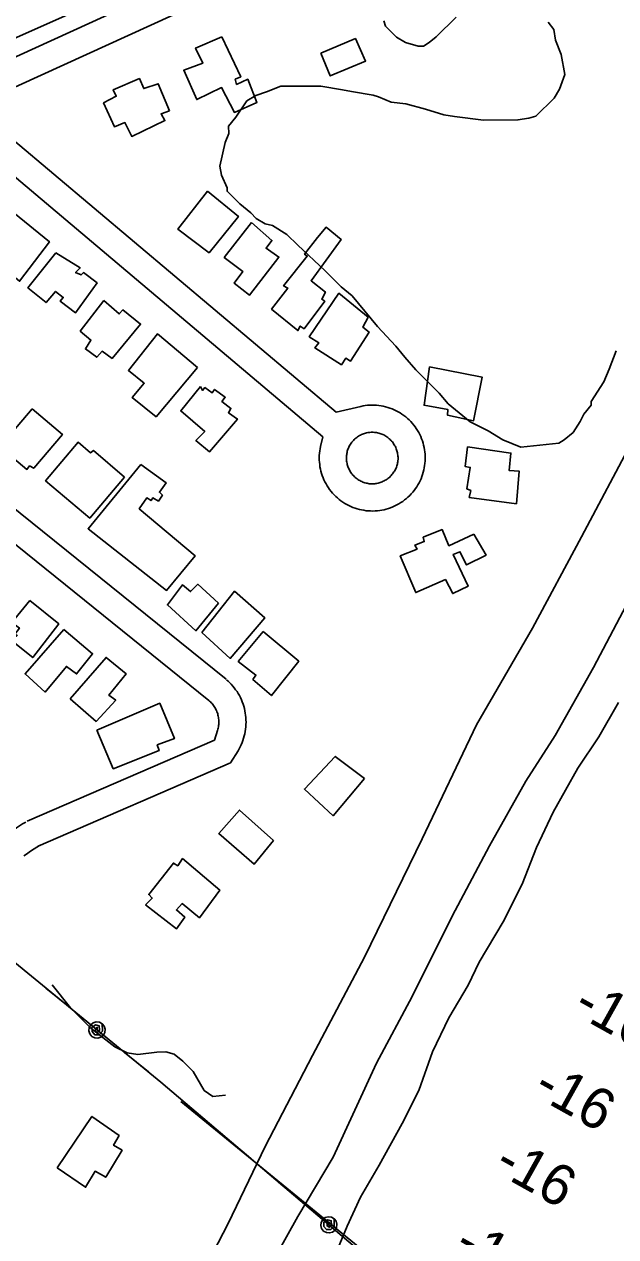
# Model space of a CAD drawing. Extents: x 3683402 to 3721514, y 487807 to 513565.
# Drawn here: x 3700485 to 3701138, y 502284 to 503622 of the extents above; entities that cross this region are included whole.
import ezdxf

# ---------------------------------------------------------------- set-up
doc = ezdxf.new("R2010")
doc.units = 0
for name, color, linetype in [('V-BLDG-OTLN', 7, 'Continuous'), ('V-LEVE-TOET', 7, 'Continuous'), ('V-ROAD-CNTR', 7, 'Continuous'), ('V-SITE-VEGE', 7, 'Continuous'), ('V-TOPO-SHOR', 7, 'Continuous'), ('V-TOPO-SPOT', 7, 'Continuous'), ('V-UTIL-LINE', 7, 'Continuous')]:
    doc.layers.add(name, color=color, linetype=linetype)

msp = doc.modelspace()

# ---------------------------------------------------------------- linework, layer by layer
at = {"layer": 'V-BLDG-OTLN'}
for points in [[(3700703.3, 503607.7), (3700724, 503563.7), (3700718, 503561), (3700719.5, 503555.3), (3700731.7, 503561), (3700741.9, 503535.5), (3700717, 503524.4), (3700702.9, 503551.7), (3700675.5, 503538.5), (3700661.1, 503570.9), (3700682.2, 503578.7), (3700674.2, 503595.4)], [(3700812.3, 503589.6), (3700850.6, 503605.8), (3700861.7, 503581.1), (3700822.8, 503564.6)], [(3700645.4, 503526.1), (3700636.2, 503522.8), (3700640.4, 503515.4), (3700603.8, 503498), (3700596.3, 503513.1), (3700584.7, 503508.6), (3700572.7, 503534.8), (3700586.7, 503542.3), (3700583.4, 503549.4), (3700612.2, 503561.7), (3700617, 503550.7), (3700633.1, 503556.1)], [(3700687.4, 503437.5), (3700721.4, 503409.7), (3700689.1, 503369.7), (3700654.5, 503395.8)], [(3700473.8, 503413.7), (3700512.9, 503381.7), (3700480, 503338.1), (3700439.7, 503371.3)], [(3700736, 503402.9), (3700758.4, 503383.3), (3700751.9, 503374.6), (3700766.2, 503364.9), (3700733.6, 503322.8), (3700716.6, 503336.1), (3700726.3, 503349), (3700705.8, 503364.4)], [(3700808.7, 503386.4), (3700818.2, 503397.8), (3700834.9, 503384.1), (3700801.7, 503338.8), (3700817.5, 503326.3), (3700813.4, 503318.3), (3700816.6, 503316.2), (3700793.8, 503285.8), (3700789.6, 503288.7), (3700787, 503283.7), (3700758, 503307.4), (3700775.8, 503330.7), (3700771.3, 503333.3), (3700797.4, 503365.9), (3700794.4, 503367.9)], [(3700520.1, 503369.5), (3700547, 503352.9), (3700541.9, 503347.8), (3700547.9, 503345.2), (3700550.5, 503347.8), (3700565.5, 503336.3), (3700541.8, 503303.5), (3700525, 503316.2), (3700528.3, 503320.4), (3700519.7, 503326.9), (3700509.3, 503314.7), (3700489.3, 503331)], [(3700864.6, 503298.5), (3700858.7, 503287.5), (3700865.6, 503282.1), (3700845.1, 503250.2), (3700840.1, 503253.5), (3700835, 503246), (3700805.8, 503264.7), (3700810.2, 503270.1), (3700799.5, 503276.9), (3700832.4, 503324.9)], [(3700573, 503317), (3700590, 503302.1), (3700594.1, 503306.6), (3700613.5, 503290.9), (3700582.1, 503253), (3700571.1, 503261), (3700565.1, 503254.4), (3700552.6, 503263.6), (3700558.8, 503273.2), (3700546.9, 503283.2)], [(3700676.4, 503243.1), (3700630.7, 503188.8), (3700604.2, 503210.1), (3700617.5, 503225.7), (3700600.2, 503239.9), (3700632.2, 503280.2)], [(3700932.4, 503243.7), (3700990.5, 503232.2), (3700980.8, 503184.3), (3700952.2, 503190.4), (3700952.5, 503196.7), (3700926.3, 503201.4)], [(3700679.7, 503222), (3700681.8, 503217.8), (3700684.5, 503220.8), (3700692.5, 503215.2), (3700695.2, 503218.8), (3700706.9, 503210.2), (3700703.3, 503205.7), (3700713.1, 503198), (3700710.5, 503193.2), (3700720.3, 503186.1), (3700689.5, 503150), (3700674.6, 503162.4), (3700684.4, 503172.6), (3700657.8, 503195.1)], [(3700493.9, 503197.6), (3700527.3, 503169.2), (3700495.6, 503131.9), (3700491.1, 503134.5), (3700488.1, 503130.6), (3700464.3, 503150.8), (3700466.6, 503153.5), (3700460.7, 503158.5)], [(3700595.9, 503122.1), (3700557.4, 503077), (3700508.7, 503118.2), (3700544.6, 503160.6), (3700558.3, 503149), (3700561.6, 503151.4)], [(3701028.1, 503092.8), (3700976, 503099.7), (3700977.8, 503107.2), (3700973.3, 503109.3), (3700977.1, 503132.8), (3700971.7, 503133.7), (3700974.3, 503155.4), (3701022, 503148.7), (3701020, 503129.6), (3701031, 503128.8)], [(3700613.8, 503136.1), (3700641.8, 503115.7), (3700634.4, 503105.5), (3700637.7, 503102.3), (3700633.2, 503095.7), (3700627, 503099.2), (3700625.2, 503096.3), (3700620.4, 503099.2), (3700612.1, 503087.3), (3700673.6, 503035.4), (3700642.2, 502997.2), (3700555.6, 503065.1)], [(3700981.2, 503059.3), (3700994.7, 503036.1), (3700973, 503025.3), (3700965.8, 503039.9), (3700958.4, 503036.9), (3700974.8, 503001.8), (3700957.9, 502993.7), (3700949.8, 503009.2), (3700917.1, 502994.8), (3700900, 503035.2), (3700918.5, 503042.7), (3700916.1, 503047.2), (3700926.5, 503051.1), (3700925.3, 503055.8), (3700946.1, 503064.2), (3700953.6, 503046.4)], [(3700699.4, 502983.1), (3700674.5, 502952.7), (3700643.1, 502981.1), (3700659.7, 503003.2), (3700668.7, 502995.8), (3700676.7, 503003.9)], [(3700681, 502950.6), (3700717.2, 502996.3), (3700750.6, 502966.9), (3700712.4, 502922.1)], [(3700491.5, 502986.2), (3700523.2, 502960.3), (3700494.5, 502923), (3700471.2, 502942), (3700477.4, 502947.3), (3700474.9, 502949), (3700479.9, 502955.7), (3700471.5, 502961.8)], [(3700528.8, 502953.9), (3700560.5, 502927.4), (3700543, 502905), (3700531.8, 502913.3), (3700508.1, 502885), (3700486.2, 502905.1)], [(3700748.6, 502951.7), (3700788, 502919.1), (3700757.8, 502881.2), (3700737.5, 502899), (3700740.7, 502903.8), (3700721.3, 502918.9)], [(3700535.8, 502877.5), (3700575.4, 502923.3), (3700597.5, 502905.2), (3700578.6, 502881.6), (3700586.2, 502876), (3700564.7, 502852.7)], [(3700565.3, 502843.2), (3700634.6, 502872.8), (3700650.9, 502833.7), (3700631.9, 502826.7), (3700633.9, 502820.5), (3700583.3, 502800.5)], [(3700860.7, 502789.8), (3700825.9, 502748.6), (3700794.2, 502778.1), (3700828.2, 502814)], [(3700760, 502721.5), (3700738.8, 502695.1), (3700699.8, 502729.1), (3700722.6, 502754.9)], [(3700618.9, 502650.5), (3700626.4, 502657.8), (3700622.5, 502661.7), (3700649.8, 502696.5), (3700654.6, 502693.4), (3700659.9, 502701.3), (3700700.8, 502666.7), (3700678.5, 502636.2), (3700659.5, 502651.8), (3700653.1, 502644.7), (3700662.3, 502636.9), (3700653.1, 502623.8)], [(3700521.4, 502360.3), (3700559.8, 502417), (3700589.8, 502395.8), (3700583.7, 502385.2), (3700593.2, 502379.6), (3700575.1, 502349.9), (3700563.4, 502356.6), (3700552.8, 502338.9)]]:
    msp.add_lwpolyline(points, close=True, dxfattribs=at)
at = {"layer": 'V-LEVE-TOET'}
for points in [[(3700682.7, 502245.7), (3700710, 502298.8), (3700750.9, 502383.9), (3700803.1, 502484.2), (3700860.6, 502592.8), (3700924, 502723.1), (3700983.9, 502848.9), (3701045.9, 502955.7), (3701100, 503056.4), (3701157, 503163.6)], [(3701174.7, 503028.7), (3701113.2, 502912.2), (3701070.8, 502837), (3701038.6, 502786.8), (3700998.6, 502715.5), (3700957.1, 502637.8), (3700913.3, 502549.3), (3700873.8, 502475.6), (3700826, 502371.9), (3700787, 502306.5), (3700760.2, 502258.3)]]:
    msp.add_lwpolyline(points, dxfattribs=at)
at = {"layer": 'V-ROAD-CNTR'}
for points in [[(3701254.5, 503941.1), (3700148.3, 503436.5)], [(3701266.9, 503913.8), (3700428.6, 503531.4)], [(3700428.6, 503531.4), (3700829.1, 503193.6)], [(3700398.4, 503517.6), (3700814.6, 503166.5)], [(3700927.2, 503137.7), (3700927.4, 503139.9), (3700927.5, 503142.4), (3700927.5, 503144.9), (3700927.4, 503147.4), (3700927.1, 503149.9), (3700926.8, 503152.4), (3700926.3, 503154.8), (3700925.8, 503157.3), (3700925.1, 503159.7), (3700924.4, 503162.1), (3700923.5, 503164.4), (3700922.5, 503166.8), (3700921.5, 503169), (3700920.3, 503171.3), (3700919.1, 503173.4), (3700917.7, 503175.6), (3700916.3, 503177.6), (3700914.8, 503179.6), (3700913.2, 503181.5), (3700911.5, 503183.4), (3700909.7, 503185.2), (3700907.9, 503186.9), (3700906, 503188.5), (3700904, 503190), (3700901.9, 503191.5), (3700899.8, 503192.9), (3700897.7, 503194.1), (3700895.5, 503195.3), (3700893.2, 503196.4), (3700890.9, 503197.4), (3700888.6, 503198.3), (3700886.2, 503199.1), (3700883.8, 503199.7), (3700881.3, 503200.3), (3700878.9, 503200.8), (3700876.4, 503201.2), (3700873.9, 503201.4), (3700871.4, 503201.6), (3700868.9, 503201.6), (3700866.4, 503201.6), (3700863.9, 503201.4), (3700861.4, 503201.1), (3700858.9, 503200.7), (3700856.4, 503200.2), (3700829.1, 503193.6)], [(3700814.6, 503166.5), (3700812, 503155.9), (3700811.5, 503153.5), (3700811.1, 503151), (3700810.9, 503148.5), (3700810.7, 503146), (3700810.6, 503143.5), (3700810.7, 503141), (3700810.8, 503138.5), (3700811.1, 503136), (3700811.4, 503133.5), (3700811.9, 503131), (3700812.5, 503128.6), (3700813.2, 503126.2), (3700813.9, 503123.8), (3700814.8, 503121.5), (3700815.8, 503119.1), (3700816.9, 503116.9), (3700818.1, 503114.7), (3700819.3, 503112.5), (3700820.7, 503110.4), (3700822.1, 503108.4), (3700823.7, 503106.4), (3700825.3, 503104.5), (3700827, 503102.6), (3700828.8, 503100.8), (3700830.6, 503099.2), (3700832.6, 503097.5), (3700834.6, 503096), (3700836.6, 503094.6), (3700838.7, 503093.2), (3700840.9, 503092), (3700843.1, 503090.8), (3700845.4, 503089.8), (3700847.7, 503088.8), (3700850.1, 503087.9), (3700852.4, 503087.2), (3700854.9, 503086.5), (3700857.3, 503085.9), (3700859.8, 503085.5), (3700862.3, 503085.1), (3700864.8, 503084.9), (3700867.3, 503084.8), (3700869.8, 503084.7), (3700872.3, 503084.8), (3700874.8, 503085), (3700877.3, 503085.3), (3700879.7, 503085.7), (3700882.2, 503086.2), (3700884.6, 503086.9), (3700887, 503087.6), (3700889.4, 503088.4), (3700891.7, 503089.3), (3700894, 503090.3), (3700896.3, 503091.5), (3700898.5, 503092.7), (3700900.6, 503094), (3700902.7, 503095.4), (3700904.7, 503096.9), (3700906.7, 503098.4), (3700908.5, 503100.1), (3700910.4, 503101.8), (3700912.1, 503103.6), (3700913.7, 503105.5), (3700915.3, 503107.5), (3700916.8, 503109.5), (3700918.2, 503111.6), (3700919.5, 503113.7), (3700920.7, 503115.9), (3700921.9, 503118.1), (3700922.9, 503120.4), (3700923.8, 503122.7), (3700924.6, 503125.1), (3700925.4, 503127.5), (3700926, 503130), (3700926.5, 503132.4), (3700926.9, 503134.9), (3700927.2, 503137.1)], [(3700897.3, 503140), (3700897.5, 503141.6), (3700897.5, 503142.8), (3700897.5, 503144), (3700897.4, 503145.2), (3700897.3, 503146.4), (3700897.1, 503147.7), (3700896.9, 503148.9), (3700896.7, 503150), (3700896.3, 503151.2), (3700896, 503152.4), (3700895.6, 503153.5), (3700895.1, 503154.7), (3700894.6, 503155.8), (3700894, 503156.8), (3700893.4, 503157.9), (3700892.7, 503158.9), (3700892, 503159.9), (3700891.3, 503160.9), (3700890.5, 503161.8), (3700889.7, 503162.7), (3700888.8, 503163.6), (3700887.9, 503164.4), (3700887, 503165.2), (3700886.1, 503166), (3700885.1, 503166.7), (3700884, 503167.4), (3700883, 503168), (3700881.9, 503168.6), (3700880.8, 503169.1), (3700879.7, 503169.6), (3700878.6, 503170), (3700877.4, 503170.4), (3700876.2, 503170.7), (3700875, 503171), (3700873.8, 503171.2), (3700872.6, 503171.4), (3700871.4, 503171.5), (3700870.2, 503171.6), (3700869, 503171.6), (3700867.8, 503171.6), (3700866.5, 503171.5), (3700865.3, 503171.4), (3700864.1, 503171.2), (3700862.9, 503170.9), (3700861.7, 503170.7), (3700860.6, 503170.3), (3700859.4, 503169.9), (3700858.3, 503169.5), (3700857.2, 503169), (3700856.1, 503168.5), (3700855, 503167.9), (3700853.9, 503167.3), (3700852.9, 503166.6), (3700851.9, 503165.9), (3700851, 503165.1), (3700850, 503164.3), (3700849.2, 503163.5), (3700848.3, 503162.6), (3700847.5, 503161.7), (3700846.7, 503160.7), (3700846.3, 503160.3)], [(3700846.6, 503160.6), (3700845.7, 503159.4), (3700845, 503158.4), (3700844.4, 503157.3), (3700843.8, 503156.2), (3700843.3, 503155.1), (3700842.8, 503154), (3700842.3, 503152.9), (3700841.9, 503151.7), (3700841.6, 503150.6), (3700841.3, 503149.4), (3700841.1, 503148.2), (3700840.9, 503147), (3700840.7, 503145.8), (3700840.7, 503144.6), (3700840.6, 503143.3), (3700840.7, 503142.1), (3700840.7, 503140.9), (3700840.8, 503139.7), (3700841, 503138.5), (3700841.3, 503137.3), (3700841.5, 503136.1), (3700841.9, 503134.9), (3700842.2, 503133.8), (3700842.7, 503132.6), (3700843.1, 503131.5), (3700843.7, 503130.4), (3700844.2, 503129.3), (3700844.9, 503128.3), (3700845.5, 503127.2), (3700846.2, 503126.2), (3700847, 503125.3), (3700847.8, 503124.3), (3700848.6, 503123.4), (3700849.5, 503122.6), (3700850.4, 503121.8), (3700851.3, 503121), (3700852.3, 503120.2), (3700853.3, 503119.5), (3700854.3, 503118.9), (3700855.4, 503118.3), (3700856.4, 503117.7), (3700857.5, 503117.2), (3700858.7, 503116.7), (3700859.8, 503116.3), (3700861, 503115.9), (3700862.2, 503115.6), (3700863.3, 503115.3), (3700864.5, 503115.1), (3700865.8, 503114.9), (3700867, 503114.8), (3700868.2, 503114.8), (3700869.4, 503114.8), (3700870.6, 503114.8), (3700871.8, 503114.9), (3700873.1, 503115), (3700874.3, 503115.2), (3700875.5, 503115.5), (3700876.6, 503115.8), (3700877.8, 503116.1), (3700879, 503116.5), (3700880.1, 503117), (3700881.2, 503117.5), (3700882.3, 503118), (3700883.4, 503118.6), (3700884.4, 503119.2), (3700885.4, 503119.9), (3700886.4, 503120.6), (3700887.4, 503121.4), (3700888.3, 503122.2), (3700889.2, 503123.1), (3700890, 503123.9), (3700890.8, 503124.9), (3700891.6, 503125.8), (3700892.3, 503126.8), (3700893, 503127.8), (3700893.6, 503128.8), (3700894.2, 503129.9), (3700894.8, 503131), (3700895.3, 503132.1), (3700895.7, 503133.2), (3700896.1, 503134.4), (3700896.5, 503135.6), (3700896.8, 503136.7), (3700897, 503137.9), (3700897.2, 503139.1), (3700897.4, 503140.7)], [(3700442.6, 503112.9), (3700707.8, 502899.1)], [(3700423.8, 503089.5), (3700689, 502875.8)], [(3700708.3, 502898.7), (3700710, 502897.2), (3700711.9, 502895.4), (3700713.6, 502893.6), (3700715.3, 502891.7), (3700716.9, 502889.7), (3700718.4, 502887.6), (3700719.9, 502885.5), (3700721.2, 502883.4), (3700722.5, 502881.2), (3700723.7, 502878.9), (3700724.7, 502876.6), (3700725.7, 502874.2), (3700726.6, 502871.8), (3700727.3, 502869.4), (3700728, 502866.9), (3700728.6, 502864.4), (3700729, 502861.9), (3700729.4, 502859.4), (3700729.7, 502856.9), (3700729.8, 502854.3), (3700729.9, 502851.8), (3700729.8, 502849.2), (3700729.6, 502846.7), (3700729.4, 502844.1), (3700729, 502841.6), (3700728.5, 502839.1), (3700727.9, 502836.6), (3700727.2, 502834.2), (3700726.4, 502831.7), (3700725.5, 502829.3), (3700724.6, 502827), (3700723.5, 502824.7), (3700722.3, 502822.4), (3700721, 502820.2), (3700712.6, 502806.9)], [(3700688.5, 502876.2), (3700689.7, 502875.1), (3700690.6, 502874.2), (3700691.5, 502873.3), (3700692.4, 502872.3), (3700693.2, 502871.3), (3700694, 502870.2), (3700694.7, 502869.2), (3700695.4, 502868.1), (3700696.1, 502866.9), (3700696.7, 502865.8), (3700697.2, 502864.6), (3700697.7, 502863.4), (3700698.2, 502862.1), (3700698.6, 502860.9), (3700698.9, 502859.6), (3700699.2, 502858.4), (3700699.4, 502857.1), (3700699.6, 502855.8), (3700699.7, 502854.5), (3700699.8, 502853.2), (3700699.8, 502851.9), (3700699.8, 502850.6), (3700699.7, 502849.3), (3700699.6, 502848), (3700699.4, 502846.7), (3700699.2, 502845.4), (3700698.9, 502844.1), (3700698.5, 502842.8), (3700695, 502831.9)], [(3700695, 502831.9), (3700488.5, 502742.5)], [(3700712.6, 502806.9), (3700500.4, 502715)], [(3700486.8, 502741.6), (3700483.4, 502739.6), (3700480, 502737.5), (3700476.6, 502735.2), (3700473.2, 502732.9), (3700469.9, 502730.6), (3700466.6, 502728.1), (3700463.4, 502725.6), (3700460.3, 502723), (3700457.2, 502720.4), (3700454.2, 502717.6), (3700451.2, 502714.9), (3700448.3, 502712), (3700445.4, 502709.1), (3700442.6, 502706.1), (3700439.9, 502703.1), (3700437.2, 502700), (3700432.7, 502694.5)], [(3700502.2, 502715.9), (3700499.1, 502714), (3700496.2, 502712.2), (3700493.3, 502710.3), (3700490.5, 502708.4), (3700487.7, 502706.4), (3700484.9, 502704.3)]]:
    msp.add_lwpolyline(points, dxfattribs=at)
at = {"layer": 'V-SITE-VEGE'}
for points in [[(3701138.3, 503261.3), (3701130.4, 503241.3), (3701124.4, 503227.4), (3701110.5, 503205.4), (3701110.5, 503201.4), (3701102.6, 503191.4), (3701098.6, 503183.4), (3701090.7, 503171.4), (3701080.8, 503163.4), (3701074.8, 503159.4), (3701032.9, 503155.3), (3701013, 503163.2), (3700997, 503173.1), (3700977, 503183), (3700953, 503202.9), (3700943, 503214.8), (3700917, 503240.6), (3700905, 503254.5), (3700895, 503266.5), (3700875, 503288.3), (3700846.9, 503322.2), (3700834.9, 503332.1), (3700816.9, 503350), (3700786.9, 503377.8), (3700774.9, 503389.7), (3700758.9, 503399.6), (3700751, 503401.6), (3700741, 503407.5), (3700735, 503413.5), (3700723, 503423.4), (3700709, 503437.4), (3700709, 503441.3), (3700702.9, 503455.3), (3700700.9, 503465.2), (3700706.8, 503491.2), (3700710.8, 503501.2), (3700710.7, 503509.1), (3700718.7, 503519.1), (3700730.6, 503537.1), (3700740.5, 503543.1), (3700752.5, 503547.2), (3700768.4, 503553.2), (3700812.3, 503553.3), (3700836.2, 503549.4), (3700846.2, 503547.5), (3700870.1, 503543.6), (3700876.1, 503541.6), (3700890.1, 503535.7), (3700906.1, 503533.7), (3700928, 503527.8), (3700948, 503521.9), (3700959.9, 503519.9), (3700991.9, 503516), (3701029.8, 503516.2), (3701041.7, 503518.2), (3701049.7, 503520.2), (3701069.6, 503540.2), (3701075.5, 503550.2), (3701081.4, 503566.2), (3701077.4, 503588.1), (3701071.3, 503604), (3701069.3, 503616), (3701063.3, 503624)], [(3700961.6, 503629.6), (3700939.7, 503607.6), (3700931.8, 503601.6), (3700925.8, 503597.6), (3700919.8, 503597.6), (3700905.8, 503601.5), (3700895.9, 503607.5), (3700883.8, 503619.4), (3700881.8, 503625.4)]]:
    msp.add_lwpolyline(points, dxfattribs=at)
at = {"layer": 'V-TOPO-SHOR'}
for points in [[(3700539.6, 503635.1), (3700464.3, 503601.5), (3700154.3, 503460.9), (3700144.8, 503459.7), (3700136.4, 503461.1), (3700131.9, 503464.1), (3700129.3, 503467.1), (3700130.1, 503470.3), (3700142.6, 503479.3), (3700468.3, 503634.6), (3700476.1, 503640), (3700474.9, 503645.6), (3700467.7, 503654.8), (3700156.4, 503825), (3699885, 503972.6), (3699721.6, 504065.2), (3699718.9, 504068.2), (3699719.5, 504071.8), (3699720.6, 504075.9), (3699722.1, 504077.7), (3699724.8, 504077.7), (3699727.8, 504077.2), (3699736.7, 504072.1)], [(3700823.4, 502252.5), (3700841.3, 502295.8), (3700856.1, 502328), (3700876.8, 502363.1), (3700902.2, 502409.1), (3700920.6, 502445.7), (3700935.7, 502488.2), (3700953.7, 502525.6), (3700974.8, 502561.8), (3700987.2, 502587), (3701013.4, 502631.5), (3701034.5, 502673.2), (3701050.4, 502713.7), (3701068.8, 502752.6), (3701095.7, 502801), (3701119.2, 502835.7), (3701140.6, 502873.5)], [(3700707.1, 502440.5), (3700693.3, 502438.8), (3700683.5, 502445.7), (3700671.7, 502466.4), (3700660.2, 502478.1), (3700650.5, 502485.8), (3700641.5, 502488.2), (3700631.4, 502487.8), (3700610.6, 502485.3), (3700598.9, 502487.2), (3700585, 502493.7), (3700558.5, 502514.3), (3700536.1, 502536.6), (3700516.1, 502562.1)]]:
    msp.add_lwpolyline(points, dxfattribs=at)
at = {"layer": 'V-UTIL-LINE'}
msp.add_line((3700657.9, 502433.5), (3701370.4, 501851.5), dxfattribs=at)
for points in [[(3706129.3, 497801), (3705828.8, 498068.5), (3705518.6, 498319.6), (3705215.1, 498577.2), (3704915.9, 498836.9), (3704693.9, 499026.2), (3704157.4, 499474.5), (3703735.3, 499831.2), (3703393.2, 500117.5), (3703044.2, 500410.8), (3702715.6, 500698.6), (3702052.3, 501252), (3701362.7, 501837.6), (3700635.7, 502454.8), (3700242, 502777.1), (3699904.9, 503059.6), (3699655.4, 503213.4), (3699371.4, 503385.3)], [(3700509.1, 502558.5), (3700535.4, 502537)], [(3700565.6, 502512.3), (3700565.8, 502515.1), (3700563.8, 502514), (3700563.6, 502511.2), (3700566.1, 502509.6), (3700568.4, 502512.1), (3700568, 502516.8), (3700563.9, 502517.9), (3700559.9, 502515.1), (3700560.1, 502510.5), (3700562.9, 502507), (3700567.7, 502507), (3700571.5, 502511.1), (3700571.3, 502519.2), (3700568.2, 502520.9), (3700564.7, 502521.2), (3700561.3, 502520.2), (3700558.6, 502518), (3700556.9, 502514.9), (3700556.6, 502511.4), (3700557.6, 502508), (3700559.9, 502505.3), (3700563, 502503.6), (3700566.5, 502503.3), (3700569.8, 502504.3), (3700572.5, 502506.6), (3700574.2, 502509.7), (3700574.5, 502513.2), (3700573.5, 502516.5), (3700571.3, 502519.2)], [(3700595.7, 502487.6), (3700622.1, 502466)], [(3700652.8, 502440.4), (3700678.7, 502418.4)], [(3700709.2, 502392.5), (3700735.1, 502370.5)], [(3700765.6, 502344.6), (3700791.5, 502322.6)], [(3700821.2, 502297.3), (3700821.5, 502300.2), (3700819.5, 502299.1), (3700819.3, 502296.3), (3700821.7, 502294.7), (3700824, 502297.2), (3700823.8, 502301.9), (3700819.6, 502303), (3700815.6, 502300.3), (3700815.8, 502295.7), (3700818.5, 502292.1), (3700823.3, 502292.1), (3700827.1, 502296.1), (3700827, 502304.2), (3700824, 502305.9), (3700820.5, 502306.3), (3700817.1, 502305.4), (3700814.4, 502303.2), (3700812.7, 502300.1), (3700812.3, 502296.6), (3700813.2, 502293.2), (3700815.4, 502290.5), (3700818.5, 502288.8), (3700822, 502288.4), (3700825.3, 502289.3), (3700828.1, 502291.5), (3700829.8, 502294.6), (3700830.2, 502298.1), (3700829.2, 502301.5), (3700827, 502304.2)]]:
    msp.add_lwpolyline(points, dxfattribs=at)

# ---------------------------------------------------------------- texts
at = {"layer": 'V-TOPO-SPOT'}
for p in [(3701088.5, 502531.5), (3701044.5, 502441.3), (3701001.3, 502357), (3700957, 502267)]:
    msp.add_text('-16', height=45, rotation=330.7933, dxfattribs=at).set_placement(p)

doc.saveas('drawing.dxf')
